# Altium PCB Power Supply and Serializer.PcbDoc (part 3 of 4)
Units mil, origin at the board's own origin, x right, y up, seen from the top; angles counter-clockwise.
Board outline 986 x 985 mil, 8 copper layers (TOP, GND1, INNER1, GND2, PWR1, INNER2, GND3, BOTTOM), stack 60.4 mil thick; 91 components, 64 nets, 288 pads, 200 vias.
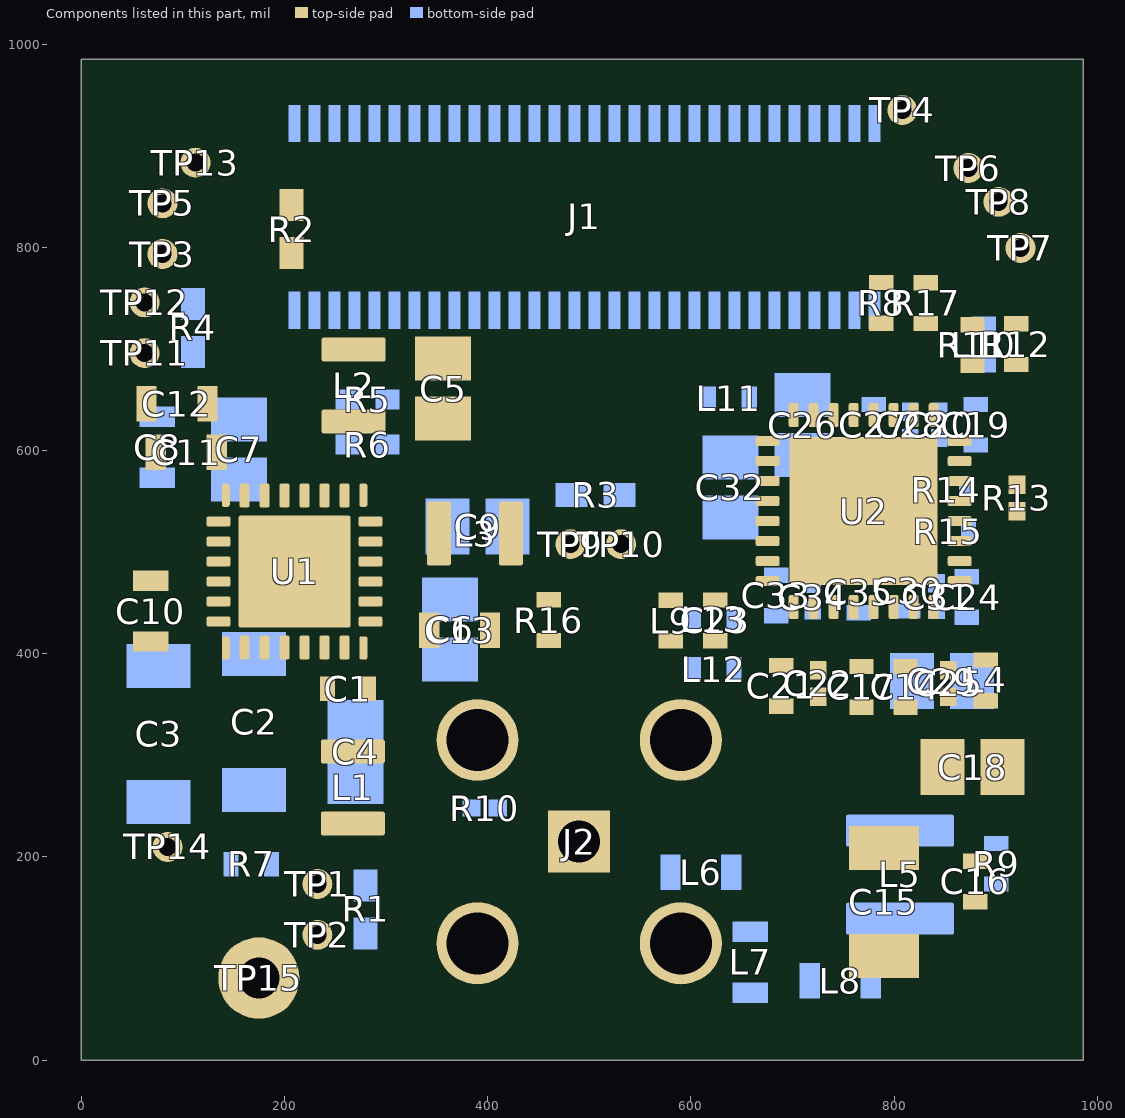
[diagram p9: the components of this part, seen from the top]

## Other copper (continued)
INNER1:
  pour cut-out: 109.26,209.8 107.4,219.16 102.1,227.1 94.16,232.4 84.8,234.26 75.44,232.4 67.5,227.1 62.2,219.16 60.34,209.8 62.2,200.44 67.5,192.5 75.44,187.2 84.8,185.34 94.16,187.2 102.1,192.5 107.4,200.44 109.26,209.8
  pour cut-out: 83.63,308.3 82.39,314.55 78.85,319.85 73.55,323.39 67.3,324.63 61.05,323.39 55.75,319.85 52.21,314.55 50.97,308.3 52.21,302.05 55.75,296.75 61.05,293.21 67.3,291.97 73.55,293.21 78.85,296.75 82.39,302.05 83.63,308.3
  pour cut-out: 126.13,308.3 124.89,314.55 121.35,319.85 116.05,323.39 109.8,324.63 103.55,323.39 98.25,319.85 94.71,314.55 93.47,308.3 94.71,302.05 98.25,296.75 103.55,293.21 109.8,291.97 116.05,293.21 121.35,296.75 124.89,302.05 126.13,308.3
  pour cut-out: 127.09,427.9 126.01,433.37 122.91,438.01 118.27,441.11 112.8,442.19 107.33,441.11 102.69,438.01 99.59,433.37 98.51,427.9 99.59,422.43 102.69,417.79 107.33,414.69 112.8,413.61 118.27,414.69 122.91,417.79 126.01,422.43 127.09,427.9
  pour cut-out: 168.63,308.3 167.39,314.55 163.85,319.85 158.55,323.39 152.3,324.63 146.05,323.39 140.75,319.85 137.21,314.55 135.97,308.3 137.21,302.05 140.75,296.75 146.05,293.21 152.3,291.97 158.55,293.21 163.85,296.75 167.39,302.05 168.63,308.3
  pour cut-out: 439.41,115.8 437.72,128.64 432.77,140.61 424.88,150.88 414.61,158.77 402.64,163.72 389.8,165.41 376.96,163.72 364.99,158.77 354.72,150.88 346.83,140.61 341.88,128.64 340.19,115.8 341.88,102.96 346.83,90.99 354.72,80.72 364.99,72.83 376.96,67.88 389.8,66.19 402.64,67.88 414.61,72.83 424.88,80.72 432.77,90.99 437.72,102.96 439.41,115.8
  pour cut-out: 323.63,205.8 322.39,212.05 318.85,217.35 313.55,220.89 307.3,222.13 301.05,220.89 295.75,217.35 292.21,212.05 290.97,205.8 292.21,199.55 295.75,194.25 301.05,190.71 307.3,189.47 313.55,190.71 318.85,194.25 322.39,199.55 323.63,205.8
  pour cut-out: 338.63,263.3 337.39,269.55 333.85,274.85 328.55,278.39 322.3,279.63 316.05,278.39 310.75,274.85 307.21,269.55 305.97,263.3 307.21,257.05 310.75,251.75 316.05,248.21 322.3,246.97 328.55,248.21 333.85,251.75 337.39,257.05 338.63,263.3
  pour cut-out: 439.41,315.8 437.72,328.64 432.77,340.61 424.88,350.88 414.61,358.77 402.64,363.72 389.8,365.41 376.96,363.72 364.99,358.77 354.72,350.88 346.83,340.61 341.88,328.64 340.19,315.8 341.88,302.96 346.83,290.99 354.72,280.72 364.99,272.83 376.96,267.88 389.8,266.19 402.64,267.88 414.61,272.83 424.88,280.72 432.77,290.99 437.72,302.96 439.41,315.8
  pour cut-out: 533.66,215.8 532.16,227.15 527.78,237.73 520.81,246.81 511.73,253.78 501.15,258.16 489.8,259.66 478.45,258.16 467.87,253.78 458.79,246.81 451.82,237.73 447.44,227.15 445.94,215.8 447.44,204.45 451.82,193.87 458.79,184.79 467.87,177.82 478.45,173.44 489.8,171.94 501.15,173.44 511.73,177.82 520.81,184.79 527.78,193.87 532.16,204.45 533.66,215.8
  pour cut-out: 639.41,115.8 637.72,128.64 632.77,140.61 624.88,150.88 614.61,158.77 602.64,163.72 589.8,165.41 576.96,163.72 564.99,158.77 554.72,150.88 546.83,140.61 541.88,128.64 540.19,115.8 541.88,102.96 546.83,90.99 554.72,80.72 564.99,72.83 576.96,67.88 589.8,66.19 602.64,67.88 614.61,72.83 624.88,80.72 632.77,90.99 637.72,102.96 639.41,115.8
  pour cut-out: 639.41,315.8 637.72,328.64 632.77,340.61 624.88,350.88 614.61,358.77 602.64,363.72 589.8,365.41 576.96,363.72 564.99,358.77 554.72,350.88 546.83,340.61 541.88,328.64 540.19,315.8 541.88,302.96 546.83,290.99 554.72,280.72 564.99,272.83 576.96,267.88 589.8,266.19 602.64,267.88 614.61,272.83 624.88,280.72 632.77,290.99 637.72,302.96 639.41,315.8
  pour cut-out: 561.13,412.71 559.89,418.96 556.35,424.26 551.05,427.8 544.8,429.04 538.55,427.8 533.25,424.26 529.71,418.96 528.47,412.71 529.71,406.46 533.25,401.16 538.55,397.62 544.8,396.38 551.05,397.62 556.35,401.16 559.89,406.46 561.13,412.71
  pour cut-out: 561.13,452.87 559.89,459.12 556.35,464.42 551.05,467.96 544.8,469.2 538.55,467.96 533.25,464.42 529.71,459.12 528.47,452.87 529.71,446.62 533.25,441.32 538.55,437.78 544.8,436.54 551.05,437.78 556.35,441.32 559.89,446.62 561.13,452.87
  pour cut-out: 724.09,410.8 723.01,416.27 719.91,420.91 715.27,424.01 709.8,425.09 704.33,424.01 699.69,420.91 696.59,416.27 695.51,410.8 696.59,405.33 699.69,400.69 704.33,397.59 709.8,396.51 715.27,397.59 719.91,400.69 723.01,405.33 724.09,410.8
  pour cut-out: 912.03,550.71 910.94,556.18 907.84,560.82 903.21,563.92 897.74,565.01 892.26,563.92 887.63,560.82 884.53,556.18 883.44,550.71 884.53,545.24 887.63,540.61 892.26,537.51 897.74,536.42 903.21,537.51 907.84,540.61 910.94,545.24 912.03,550.71
  pour cut-out: 934.09,658.3 933.01,663.77 929.91,668.41 925.27,671.51 919.8,672.59 914.33,671.51 909.69,668.41 906.59,663.77 905.51,658.3 906.59,652.83 909.69,648.19 914.33,645.09 919.8,644.01 925.27,645.09 929.91,648.19 933.01,652.83 934.09,658.3
  pour cut-out: 214.25,574.8 213.17,580.27 210.07,584.91 205.43,588.01 199.96,589.09 194.49,588.01 189.85,584.91 186.75,580.27 185.67,574.8 186.75,569.33 189.85,564.69 194.49,561.59 199.96,560.51 205.43,561.59 210.07,564.69 213.17,569.33 214.25,574.8
  pour cut-out: 275.8,575.8 274.72,581.27 271.62,585.91 266.98,589.01 261.51,590.09 256.04,589.01 251.4,585.91 248.3,581.27 247.22,575.8 248.3,570.33 251.4,565.69 256.04,562.59 261.51,561.51 266.98,562.59 271.62,565.69 274.72,570.33 275.8,575.8
  text ".Layer_Name" at 577,-858.49 h60
GND2:
  pour cut-out: 323.63,205.8 322.39,212.05 318.85,217.35 313.55,220.89 307.3,222.13 301.05,220.89 295.75,217.35 292.21,212.05 290.97,205.8 292.21,199.55 295.75,194.25 301.05,190.71 307.3,189.47 313.55,190.71 318.85,194.25 322.39,199.55 323.63,205.8
  pour cut-out: 911.96,550.94 910.87,556.41 907.77,561.05 903.14,564.15 897.67,565.24 892.2,564.15 887.56,561.05 884.46,556.41 883.37,550.94 884.46,545.47 887.56,540.83 892.2,537.73 897.67,536.65 903.14,537.73 907.77,540.83 910.87,545.47 911.96,550.94
  pour cut-out: 935.09,590.8 934.01,596.27 930.91,600.91 926.27,604.01 920.8,605.09 915.33,604.01 910.69,600.91 907.59,596.27 906.51,590.8 907.59,585.33 910.69,580.69 915.33,577.59 920.8,576.51 926.27,577.59 930.91,580.69 934.01,585.33 935.09,590.8
  pour cut-out: 774.49,893.3 773.41,898.77 770.31,903.41 765.67,906.51 760.2,907.59 754.73,906.51 750.09,903.41 746.99,898.77 745.91,893.3 746.99,887.83 750.09,883.19 754.73,880.09 760.2,879.01 765.67,880.09 770.31,883.19 773.41,887.83 774.49,893.3
  pour cut-out: 735.09,893.3 734.01,898.77 730.91,903.41 726.27,906.51 720.8,907.59 715.33,906.51 710.69,903.41 707.59,898.77 706.51,893.3 707.59,887.83 710.69,883.19 715.33,880.09 720.8,879.01 726.27,880.09 730.91,883.19 734.01,887.83 735.09,893.3
  pour cut-out: 724.09,410.8 723.01,416.27 719.91,420.91 715.27,424.01 709.8,425.09 704.33,424.01 699.69,420.91 696.59,416.27 695.51,410.8 696.59,405.33 699.69,400.69 704.33,397.59 709.8,396.51 715.27,397.59 719.91,400.69 723.01,405.33 724.09,410.8
  pour cut-out: 695.69,893.3 694.61,898.77 691.51,903.41 686.87,906.51 681.4,907.59 675.93,906.51 671.29,903.41 668.19,898.77 667.11,893.3 668.19,887.83 671.29,883.19 675.93,880.09 681.4,879.01 686.87,880.09 691.51,883.19 694.61,887.83 695.69,893.3
  pour cut-out: 561.13,452.87 559.89,459.12 556.35,464.42 551.05,467.96 544.8,469.2 538.55,467.96 533.25,464.42 529.71,459.12 528.47,452.87 529.71,446.62 533.25,441.32 538.55,437.78 544.8,436.54 551.05,437.78 556.35,441.32 559.89,446.62 561.13,452.87
  pour cut-out: 561.13,412.71 559.89,418.96 556.35,424.26 551.05,427.8 544.8,429.04 538.55,427.8 533.25,424.26 529.71,418.96 528.47,412.71 529.71,406.46 533.25,401.16 538.55,397.62 544.8,396.38 551.05,397.62 556.35,401.16 559.89,406.46 561.13,412.71
  pour cut-out: 639.41,315.8 637.72,328.64 632.77,340.61 624.88,350.88 614.61,358.77 602.64,363.72 589.8,365.41 576.96,363.72 564.99,358.77 554.72,350.88 546.83,340.61 541.88,328.64 540.19,315.8 541.88,302.96 546.83,290.99 554.72,280.72 564.99,272.83 576.96,267.88 589.8,266.19 602.64,267.88 614.61,272.83 624.88,280.72 632.77,290.99 637.72,302.96 639.41,315.8
  pour cut-out: 639.41,115.8 637.72,128.64 632.77,140.61 624.88,150.88 614.61,158.77 602.64,163.72 589.8,165.41 576.96,163.72 564.99,158.77 554.72,150.88 546.83,140.61 541.88,128.64 540.19,115.8 541.88,102.96 546.83,90.99 554.72,80.72 564.99,72.83 576.96,67.88 589.8,66.19 602.64,67.88 614.61,72.83 624.88,80.72 632.77,90.99 637.72,102.96 639.41,115.8
  pour cut-out: 477.09,385.8 476.01,391.27 472.91,395.91 468.27,399.01 462.8,400.09 457.33,399.01 452.69,395.91 449.59,391.27 448.51,385.8 449.59,380.33 452.69,375.69 457.33,372.59 462.8,371.51 468.27,372.59 472.91,375.69 476.01,380.33 477.09,385.8
  pour cut-out: 533.66,215.8 532.16,227.15 527.78,237.73 520.81,246.81 511.73,253.78 501.15,258.16 489.8,259.66 478.45,258.16 467.87,253.78 458.79,246.81 451.82,237.73 447.44,227.15 445.94,215.8 447.44,204.45 451.82,193.87 458.79,184.79 467.87,177.82 478.45,173.44 489.8,171.94 501.15,173.44 511.73,177.82 520.81,184.79 527.78,193.87 532.16,204.45 533.66,215.8
  pour cut-out: 341.39,885.8 340.31,891.27 337.21,895.91 332.57,899.01 327.1,900.09 321.63,899.01 316.99,895.91 313.89,891.27 312.81,885.8 313.89,880.33 316.99,875.69 321.63,872.59 327.1,871.51 332.57,872.59 337.21,875.69 340.31,880.33 341.39,885.8
  pour cut-out: 439.41,115.8 437.72,128.64 432.77,140.61 424.88,150.88 414.61,158.77 402.64,163.72 389.8,165.41 376.96,163.72 364.99,158.77 354.72,150.88 346.83,140.61 341.88,128.64 340.19,115.8 341.88,102.96 346.83,90.99 354.72,80.72 364.99,72.83 376.96,67.88 389.8,66.19 402.64,67.88 414.61,72.83 424.88,80.72 432.77,90.99 437.72,102.96 439.41,115.8
  pour cut-out: 266.13,865.8 264.89,872.05 261.35,877.35 256.05,880.89 249.8,882.13 243.55,880.89 238.25,877.35 234.71,872.05 233.47,865.8 234.71,859.55 238.25,854.25 243.55,850.71 249.8,849.47 256.05,850.71 261.35,854.25 264.89,859.55 266.13,865.8
  pour cut-out: 293.63,890.8 292.39,897.05 288.85,902.35 283.55,905.89 277.3,907.13 271.05,905.89 265.75,902.35 262.21,897.05 260.97,890.8 262.21,884.55 265.75,879.25 271.05,875.71 277.3,874.47 283.55,875.71 288.85,879.25 292.39,884.55 293.63,890.8
  pour cut-out: 275.8,575.8 274.72,581.27 271.62,585.91 266.98,589.01 261.51,590.09 256.04,589.01 251.4,585.91 248.3,581.27 247.22,575.8 248.3,570.33 251.4,565.69 256.04,562.59 261.51,561.51 266.98,562.59 271.62,565.69 274.72,570.33 275.8,575.8
  pour cut-out: 233.93,379.8 232.85,385.27 229.75,389.91 225.11,393.01 219.64,394.09 214.17,393.01 209.53,389.91 206.43,385.27 205.35,379.8 206.43,374.33 209.53,369.69 214.17,366.59 219.64,365.51 225.11,366.59 229.75,369.69 232.85,374.33 233.93,379.8
  pour cut-out: 214.25,574.8 213.17,580.27 210.07,584.91 205.43,588.01 199.96,589.09 194.49,588.01 189.85,584.91 186.75,580.27 185.67,574.8 186.75,569.33 189.85,564.69 194.49,561.59 199.96,560.51 205.43,561.59 210.07,564.69 213.17,569.33 214.25,574.8
  pour cut-out: 211.13,308.3 209.89,314.55 206.35,319.85 201.05,323.39 194.8,324.63 188.55,323.39 183.25,319.85 179.71,314.55 178.47,308.3 179.71,302.05 183.25,296.75 188.55,293.21 194.8,291.97 201.05,293.21 206.35,296.75 209.89,302.05 211.13,308.3
  pour cut-out: 168.63,308.3 167.39,314.55 163.85,319.85 158.55,323.39 152.3,324.63 146.05,323.39 140.75,319.85 137.21,314.55 135.97,308.3 137.21,302.05 140.75,296.75 146.05,293.21 152.3,291.97 158.55,293.21 163.85,296.75 167.39,302.05 168.63,308.3
  pour cut-out: 161.43,220.8 160.35,226.27 157.25,230.91 152.61,234.01 147.14,235.09 141.67,234.01 137.03,230.91 133.93,226.27 132.85,220.8 133.93,215.33 137.03,210.69 141.67,207.59 147.14,206.51 152.61,207.59 157.25,210.69 160.35,215.33 161.43,220.8
  pour cut-out: 127.09,427.9 126.01,433.37 122.91,438.01 118.27,441.11 112.8,442.19 107.33,441.11 102.69,438.01 99.59,433.37 98.51,427.9 99.59,422.43 102.69,417.79 107.33,414.69 112.8,413.61 118.27,414.69 122.91,417.79 126.01,422.43 127.09,427.9
  pour cut-out: 126.13,308.3 124.89,314.55 121.35,319.85 116.05,323.39 109.8,324.63 103.55,323.39 98.25,319.85 94.71,314.55 93.47,308.3 94.71,302.05 98.25,296.75 103.55,293.21 109.8,291.97 116.05,293.21 121.35,296.75 124.89,302.05 126.13,308.3
  pour cut-out: 83.63,308.3 82.39,314.55 78.85,319.85 73.55,323.39 67.3,324.63 61.05,323.39 55.75,319.85 52.21,314.55 50.97,308.3 52.21,302.05 55.75,296.75 61.05,293.21 67.3,291.97 73.55,293.21 78.85,296.75 82.39,302.05 83.63,308.3
  pour cut-out: 109.26,209.8 107.4,219.16 102.1,227.1 94.16,232.4 84.8,234.26 75.44,232.4 67.5,227.1 62.2,219.16 60.34,209.8 62.2,200.44 67.5,192.5 75.44,187.2 84.8,185.34 94.16,187.2 102.1,192.5 107.4,200.44 109.26,209.8
  pour cut-out: 327.09,680.8 326.01,686.27 322.91,690.91 318.27,694.01 312.8,695.09 307.33,694.01 302.69,690.91 299.59,686.27 298.51,680.8 299.59,675.33 302.69,670.69 307.33,667.59 312.8,666.51 318.27,667.59 322.91,670.69 326.01,675.33 327.09,680.8
  pour cut-out: 934.09,658.3 933.01,663.77 929.91,668.41 925.27,671.51 919.8,672.59 914.33,671.51 909.69,668.41 906.59,663.77 905.51,658.3 906.59,652.83 909.69,648.19 914.33,645.09 919.8,644.01 925.27,645.09 929.91,648.19 933.01,652.83 934.09,658.3
  pour cut-out: 239.09,253.3 238.01,258.77 234.91,263.41 230.27,266.51 224.8,267.59 219.33,266.51 214.69,263.41 211.59,258.77 210.51,253.3 211.59,247.83 214.69,243.19 219.33,240.09 224.8,239.01 230.27,240.09 234.91,243.19 238.01,247.83 239.09,253.3
  pour cut-out: 201.59,220.3 200.51,225.77 197.41,230.41 192.77,233.51 187.3,234.59 181.83,233.51 177.19,230.41 174.09,225.77 173.01,220.3 174.09,214.83 177.19,210.19 181.83,207.09 187.3,206.01 192.77,207.09 197.41,210.19 200.51,214.83 201.59,220.3
  pour cut-out: 338.63,263.3 337.39,269.55 333.85,274.85 328.55,278.39 322.3,279.63 316.05,278.39 310.75,274.85 307.21,269.55 305.97,263.3 307.21,257.05 310.75,251.75 316.05,248.21 322.3,246.97 328.55,248.21 333.85,251.75 337.39,257.05 338.63,263.3
  pour cut-out: 439.41,315.8 437.72,328.64 432.77,340.61 424.88,350.88 414.61,358.77 402.64,363.72 389.8,365.41 376.96,363.72 364.99,358.77 354.72,350.88 346.83,340.61 341.88,328.64 340.19,315.8 341.88,302.96 346.83,290.99 354.72,280.72 364.99,272.83 376.96,267.88 389.8,266.19 402.64,267.88 414.61,272.83 424.88,280.72 432.77,290.99 437.72,302.96 439.41,315.8
  text ".Layer_Name" at 577,-858.49 h60
PWR1:
  pour cut-out: 416.59,393.3 415.51,398.77 412.41,403.41 407.77,406.51 402.3,407.59 396.83,406.51 392.19,403.41 389.09,398.77 388.01,393.3 389.09,387.83 392.19,383.19 396.83,380.09 402.3,379.01 407.77,380.09 412.41,383.19 415.51,387.83 416.59,393.3
  pour cut-out: 338.63,263.3 337.39,269.55 333.85,274.85 328.55,278.39 322.3,279.63 316.05,278.39 310.75,274.85 307.21,269.55 305.97,263.3 307.21,257.05 310.75,251.75 316.05,248.21 322.3,246.97 328.55,248.21 333.85,251.75 337.39,257.05 338.63,263.3
  pour cut-out: 323.63,205.8 322.39,212.05 318.85,217.35 313.55,220.89 307.3,222.13 301.05,220.89 295.75,217.35 292.21,212.05 290.97,205.8 292.21,199.55 295.75,194.25 301.05,190.71 307.3,189.47 313.55,190.71 318.85,194.25 322.39,199.55 323.63,205.8
  pour cut-out: 275.8,575.8 274.72,581.27 271.62,585.91 266.98,589.01 261.51,590.09 256.04,589.01 251.4,585.91 248.3,581.27 247.22,575.8 248.3,570.33 251.4,565.69 256.04,562.59 261.51,561.51 266.98,562.59 271.62,565.69 274.72,570.33 275.8,575.8
  pour cut-out: 224.09,520.8 223.01,526.27 219.91,530.91 215.27,534.01 209.8,535.09 204.33,534.01 199.69,530.91 196.59,526.27 195.51,520.8 196.59,515.33 199.69,510.69 204.33,507.59 209.8,506.51 215.27,507.59 219.91,510.69 223.01,515.33 224.09,520.8
  pour cut-out: 264.09,520.8 263.01,526.27 259.91,530.91 255.27,534.01 249.8,535.09 244.33,534.01 239.69,530.91 236.59,526.27 235.51,520.8 236.59,515.33 239.69,510.69 244.33,507.59 249.8,506.51 255.27,507.59 259.91,510.69 263.01,515.33 264.09,520.8
  pour cut-out: 224.09,440.8 223.01,446.27 219.91,450.91 215.27,454.01 209.8,455.09 204.33,454.01 199.69,450.91 196.59,446.27 195.51,440.8 196.59,435.33 199.69,430.69 204.33,427.59 209.8,426.51 215.27,427.59 219.91,430.69 223.01,435.33 224.09,440.8
  pour cut-out: 264.09,440.8 263.01,446.27 259.91,450.91 255.27,454.01 249.8,455.09 244.33,454.01 239.69,450.91 236.59,446.27 235.51,440.8 236.59,435.33 239.69,430.69 244.33,427.59 249.8,426.51 255.27,427.59 259.91,430.69 263.01,435.33 264.09,440.8
  pour cut-out: 264.09,480.8 263.01,486.27 259.91,490.91 255.27,494.01 249.8,495.09 244.33,494.01 239.69,490.91 236.59,486.27 235.51,480.8 236.59,475.33 239.69,470.69 244.33,467.59 249.8,466.51 255.27,467.59 259.91,470.69 263.01,475.33 264.09,480.8
  pour cut-out: 224.09,480.8 223.01,486.27 219.91,490.91 215.27,494.01 209.8,495.09 204.33,494.01 199.69,490.91 196.59,486.27 195.51,480.8 196.59,475.33 199.69,470.69 204.33,467.59 209.8,466.51 215.27,467.59 219.91,470.69 223.01,475.33 224.09,480.8
  pour cut-out: 233.93,379.8 232.85,385.27 229.75,389.91 225.11,393.01 219.64,394.09 214.17,393.01 209.53,389.91 206.43,385.27 205.35,379.8 206.43,374.33 209.53,369.69 214.17,366.59 219.64,365.51 225.11,366.59 229.75,369.69 232.85,374.33 233.93,379.8
  pour cut-out: 239.09,253.3 238.01,258.77 234.91,263.41 230.27,266.51 224.8,267.59 219.33,266.51 214.69,263.41 211.59,258.77 210.51,253.3 211.59,247.83 214.69,243.19 219.33,240.09 224.8,239.01 230.27,240.09 234.91,243.19 238.01,247.83 239.09,253.3
  pour cut-out: 214.25,574.8 213.17,580.27 210.07,584.91 205.43,588.01 199.96,589.09 194.49,588.01 189.85,584.91 186.75,580.27 185.67,574.8 186.75,569.33 189.85,564.69 194.49,561.59 199.96,560.51 205.43,561.59 210.07,564.69 213.17,569.33 214.25,574.8
  pour cut-out: 184.09,520.8 183.01,526.27 179.91,530.91 175.27,534.01 169.8,535.09 164.33,534.01 159.69,530.91 156.59,526.27 155.51,520.8 156.59,515.33 159.69,510.69 164.33,507.59 169.8,506.51 175.27,507.59 179.91,510.69 183.01,515.33 184.09,520.8
  pour cut-out: 184.09,440.8 183.01,446.27 179.91,450.91 175.27,454.01 169.8,455.09 164.33,454.01 159.69,450.91 156.59,446.27 155.51,440.8 156.59,435.33 159.69,430.69 164.33,427.59 169.8,426.51 175.27,427.59 179.91,430.69 183.01,435.33 184.09,440.8
  pour cut-out: 184.09,480.8 183.01,486.27 179.91,490.91 175.27,494.01 169.8,495.09 164.33,494.01 159.69,490.91 156.59,486.27 155.51,480.8 156.59,475.33 159.69,470.69 164.33,467.59 169.8,466.51 175.27,467.59 179.91,470.69 183.01,475.33 184.09,480.8
  pour cut-out: 184.09,350.8 183.01,356.27 179.91,360.91 175.27,364.01 169.8,365.09 164.33,364.01 159.69,360.91 156.59,356.27 155.51,350.8 156.59,345.33 159.69,340.69 164.33,337.59 169.8,336.51 175.27,337.59 179.91,340.69 183.01,345.33 184.09,350.8
  pour cut-out: 211.13,308.3 209.89,314.55 206.35,319.85 201.05,323.39 194.8,324.63 188.55,323.39 183.25,319.85 179.71,314.55 178.47,308.3 179.71,302.05 183.25,296.75 188.55,293.21 194.8,291.97 201.05,293.21 206.35,296.75 209.89,302.05 211.13,308.3
  pour cut-out: 168.63,308.3 167.39,314.55 163.85,319.85 158.55,323.39 152.3,324.63 146.05,323.39 140.75,319.85 137.21,314.55 135.97,308.3 137.21,302.05 140.75,296.75 146.05,293.21 152.3,291.97 158.55,293.21 163.85,296.75 167.39,302.05 168.63,308.3
  pour cut-out: 161.43,220.8 160.35,226.27 157.25,230.91 152.61,234.01 147.14,235.09 141.67,234.01 137.03,230.91 133.93,226.27 132.85,220.8 133.93,215.33 137.03,210.69 141.67,207.59 147.14,206.51 152.61,207.59 157.25,210.69 160.35,215.33 161.43,220.8
  pour cut-out: 201.59,220.3 200.51,225.77 197.41,230.41 192.77,233.51 187.3,234.59 181.83,233.51 177.19,230.41 174.09,225.77 173.01,220.3 174.09,214.83 177.19,210.19 181.83,207.09 187.3,206.01 192.77,207.09 197.41,210.19 200.51,214.83 201.59,220.3
  pour cut-out: 128.59,561.3 127.51,566.77 124.41,571.41 119.77,574.51 114.3,575.59 108.83,574.51 104.19,571.41 101.09,566.77 100.01,561.3 101.09,555.83 104.19,551.19 108.83,548.09 114.3,547.01 119.77,548.09 124.41,551.19 127.51,555.83 128.59,561.3
  pour cut-out: 89.09,350.8 88.01,356.27 84.91,360.91 80.27,364.01 74.8,365.09 69.33,364.01 64.69,360.91 61.59,356.27 60.51,350.8 61.59,345.33 64.69,340.69 69.33,337.59 74.8,336.51 80.27,337.59 84.91,340.69 88.01,345.33 89.09,350.8
  pour cut-out: 126.13,308.3 124.89,314.55 121.35,319.85 116.05,323.39 109.8,324.63 103.55,323.39 98.25,319.85 94.71,314.55 93.47,308.3 94.71,302.05 98.25,296.75 103.55,293.21 109.8,291.97 116.05,293.21 121.35,296.75 124.89,302.05 126.13,308.3
  pour cut-out: 83.63,308.3 82.39,314.55 78.85,319.85 73.55,323.39 67.3,324.63 61.05,323.39 55.75,319.85 52.21,314.55 50.97,308.3 52.21,302.05 55.75,296.75 61.05,293.21 67.3,291.97 73.55,293.21 78.85,296.75 82.39,302.05 83.63,308.3
  pour cut-out: 109.26,209.8 107.4,219.16 102.1,227.1 94.16,232.4 84.8,234.26 75.44,232.4 67.5,227.1 62.2,219.16 60.34,209.8 62.2,200.44 67.5,192.5 75.44,187.2 84.8,185.34 94.16,187.2 102.1,192.5 107.4,200.44 109.26,209.8
  pour cut-out: 912.14,550.64 911.05,556.11 907.95,560.74 903.32,563.84 897.85,564.93 892.38,563.84 887.74,560.74 884.64,556.11 883.55,550.64 884.64,545.17 887.74,540.53 892.38,537.43 897.85,536.34 903.32,537.43 907.95,540.53 911.05,545.17 912.14,550.64
  pour cut-out: 824.09,268.3 823.01,273.77 819.91,278.41 815.27,281.51 809.8,282.59 804.33,281.51 799.69,278.41 796.59,273.77 795.51,268.3 796.59,262.83 799.69,258.19 804.33,255.09 809.8,254.01 815.27,255.09 819.91,258.19 823.01,262.83 824.09,268.3
  pour cut-out: 735.09,893.3 734.01,898.77 730.91,903.41 726.27,906.51 720.8,907.59 715.33,906.51 710.69,903.41 707.59,898.77 706.51,893.3 707.59,887.83 710.69,883.19 715.33,880.09 720.8,879.01 726.27,880.09 730.91,883.19 734.01,887.83 735.09,893.3
  pour cut-out: 724.09,410.8 723.01,416.27 719.91,420.91 715.27,424.01 709.8,425.09 704.33,424.01 699.69,420.91 696.59,416.27 695.51,410.8 696.59,405.33 699.69,400.69 704.33,397.59 709.8,396.51 715.27,397.59 719.91,400.69 723.01,405.33 724.09,410.8
  pour cut-out: 728.63,123.3 727.39,129.55 723.85,134.85 718.55,138.39 712.3,139.63 706.05,138.39 700.75,134.85 697.21,129.55 695.97,123.3 697.21,117.05 700.75,111.75 706.05,108.21 712.3,106.97 718.55,108.21 723.85,111.75 727.39,117.05 728.63,123.3
  pour cut-out: 695.69,893.3 694.61,898.77 691.51,903.41 686.87,906.51 681.4,907.59 675.93,906.51 671.29,903.41 668.19,898.77 667.11,893.3 668.19,887.83 671.29,883.19 675.93,880.09 681.4,879.01 686.87,880.09 691.51,883.19 694.61,887.83 695.69,893.3
  pour cut-out: 674.09,690.8 673.01,696.27 669.91,700.91 665.27,704.01 659.8,705.09 654.33,704.01 649.69,700.91 646.59,696.27 645.51,690.8 646.59,685.33 649.69,680.69 654.33,677.59 659.8,676.51 665.27,677.59 669.91,680.69 673.01,685.33 674.09,690.8
  pour cut-out: 674.09,343.22 673.01,348.69 669.91,353.33 665.27,356.43 659.8,357.51 654.33,356.43 649.69,353.33 646.59,348.69 645.51,343.22 646.59,337.75 649.69,333.11 654.33,330.01 659.8,328.93 665.27,330.01 669.91,333.11 673.01,337.75 674.09,343.22
  pour cut-out: 701.13,220.8 699.89,227.05 696.35,232.35 691.05,235.89 684.8,237.13 678.55,235.89 673.25,232.35 669.71,227.05 668.47,220.8 669.71,214.55 673.25,209.25 678.55,205.71 684.8,204.47 691.05,205.71 696.35,209.25 699.89,214.55 701.13,220.8
  pour cut-out: 713.63,168.3 712.39,174.55 708.85,179.85 703.55,183.39 697.3,184.63 691.05,183.39 685.75,179.85 682.21,174.55 680.97,168.3 682.21,162.05 685.75,156.75 691.05,153.21 697.3,151.97 703.55,153.21 708.85,156.75 712.39,162.05 713.63,168.3
  pour cut-out: 639.62,315.8 637.92,328.69 632.94,340.71 625.03,351.03 614.71,358.94 602.69,363.92 589.8,365.62 576.91,363.92 564.89,358.94 554.57,351.03 546.66,340.71 541.68,328.69 539.98,315.8 541.68,302.91 546.66,290.89 554.57,280.57 564.89,272.66 576.91,267.68 589.8,265.98 602.69,267.68 614.71,272.66 625.03,280.57 632.94,290.89 637.92,302.91 639.62,315.8
  pour cut-out: 518.59,704.7 517.51,710.17 514.41,714.81 509.77,717.91 504.3,718.99 498.83,717.91 494.19,714.81 491.09,710.17 490.01,704.7 491.09,699.23 494.19,694.59 498.83,691.49 504.3,690.41 509.77,691.49 514.41,694.59 517.51,699.23 518.59,704.7
  pour cut-out: 529.09,320.8 528.01,326.27 524.91,330.91 520.27,334.01 514.8,335.09 509.33,334.01 504.69,330.91 501.59,326.27 500.51,320.8 501.59,315.33 504.69,310.69 509.33,307.59 514.8,306.51 520.27,307.59 524.91,310.69 528.01,315.33 529.09,320.8
  pour cut-out: 529.09,110.8 528.01,116.27 524.91,120.91 520.27,124.01 514.8,125.09 509.33,124.01 504.69,120.91 501.59,116.27 500.51,110.8 501.59,105.33 504.69,100.69 509.33,97.59 514.8,96.51 520.27,97.59 524.91,100.69 528.01,105.33 529.09,110.8
  pour cut-out: 391.59,788.3 390.51,793.77 387.41,798.41 382.77,801.51 377.3,802.59 371.83,801.51 367.19,798.41 364.09,793.77 363.01,788.3 364.09,782.83 367.19,778.19 371.83,775.09 377.3,774.01 382.77,775.09 387.41,778.19 390.51,782.83 391.59,788.3
  pour cut-out: 341.39,885.8 340.31,891.27 337.21,895.91 332.57,899.01 327.1,900.09 321.63,899.01 316.99,895.91 313.89,891.27 312.81,885.8 313.89,880.33 316.99,875.69 321.63,872.59 327.1,871.51 332.57,872.59 337.21,875.69 340.31,880.33 341.39,885.8
  text ".Layer_Name" at 577,-858.49 h60
INNER2:
  pour cut-out: 533.66,215.8 532.16,227.15 527.78,237.73 520.81,246.81 511.73,253.78 501.15,258.16 489.8,259.66 478.45,258.16 467.87,253.78 458.79,246.81 451.82,237.73 447.44,227.15 445.94,215.8 447.44,204.45 451.82,193.87 458.79,184.79 467.87,177.82 478.45,173.44 489.8,171.94 501.15,173.44 511.73,177.82 520.81,184.79 527.78,193.87 532.16,204.45 533.66,215.8
  pour cut-out: 109.06,209.8 107.21,219.08 101.95,226.95 94.08,232.21 84.8,234.06 75.52,232.21 67.65,226.95 62.39,219.08 60.54,209.8 62.39,200.52 67.65,192.65 75.52,187.39 84.8,185.54 94.08,187.39 101.95,192.65 107.21,200.52 109.06,209.8
  pour cut-out: 89.09,350.8 88.01,356.27 84.91,360.91 80.27,364.01 74.8,365.09 69.33,364.01 64.69,360.91 61.59,356.27 60.51,350.8 61.59,345.33 64.69,340.69 69.33,337.59 74.8,336.51 80.27,337.59 84.91,340.69 88.01,345.33 89.09,350.8
  pour cut-out: 128.59,561.3 127.51,566.77 124.41,571.41 119.77,574.51 114.3,575.59 108.83,574.51 104.19,571.41 101.09,566.77 100.01,561.3 101.09,555.83 104.19,551.19 108.83,548.09 114.3,547.01 119.77,548.09 124.41,551.19 127.51,555.83 128.59,561.3
  pour cut-out: 201.59,220.3 200.51,225.77 197.41,230.41 192.77,233.51 187.3,234.59 181.83,233.51 177.19,230.41 174.09,225.77 173.01,220.3 174.09,214.83 177.19,210.19 181.83,207.09 187.3,206.01 192.77,207.09 197.41,210.19 200.51,214.83 201.59,220.3
  pour cut-out: 161.43,220.8 160.35,226.27 157.25,230.91 152.61,234.01 147.14,235.09 141.67,234.01 137.03,230.91 133.93,226.27 132.85,220.8 133.93,215.33 137.03,210.69 141.67,207.59 147.14,206.51 152.61,207.59 157.25,210.69 160.35,215.33 161.43,220.8
  pour cut-out: 184.09,480.8 183.01,486.27 179.91,490.91 175.27,494.01 169.8,495.09 164.33,494.01 159.69,490.91 156.59,486.27 155.51,480.8 156.59,475.33 159.69,470.69 164.33,467.59 169.8,466.51 175.27,467.59 179.91,470.69 183.01,475.33 184.09,480.8
  pour cut-out: 184.09,440.8 183.01,446.27 179.91,450.91 175.27,454.01 169.8,455.09 164.33,454.01 159.69,450.91 156.59,446.27 155.51,440.8 156.59,435.33 159.69,430.69 164.33,427.59 169.8,426.51 175.27,427.59 179.91,430.69 183.01,435.33 184.09,440.8
  pour cut-out: 184.09,520.8 183.01,526.27 179.91,530.91 175.27,534.01 169.8,535.09 164.33,534.01 159.69,530.91 156.59,526.27 155.51,520.8 156.59,515.33 159.69,510.69 164.33,507.59 169.8,506.51 175.27,507.59 179.91,510.69 183.01,515.33 184.09,520.8
  pour cut-out: 214.25,574.8 213.17,580.27 210.07,584.91 205.43,588.01 199.96,589.09 194.49,588.01 189.85,584.91 186.75,580.27 185.67,574.8 186.75,569.33 189.85,564.69 194.49,561.59 199.96,560.51 205.43,561.59 210.07,564.69 213.17,569.33 214.25,574.8
  pour cut-out: 239.09,253.3 238.01,258.77 234.91,263.41 230.27,266.51 224.8,267.59 219.33,266.51 214.69,263.41 211.59,258.77 210.51,253.3 211.59,247.83 214.69,243.19 219.33,240.09 224.8,239.01 230.27,240.09 234.91,243.19 238.01,247.83 239.09,253.3
  pour cut-out: 224.09,480.8 223.01,486.27 219.91,490.91 215.27,494.01 209.8,495.09 204.33,494.01 199.69,490.91 196.59,486.27 195.51,480.8 196.59,475.33 199.69,470.69 204.33,467.59 209.8,466.51 215.27,467.59 219.91,470.69 223.01,475.33 224.09,480.8
  pour cut-out: 264.09,480.8 263.01,486.27 259.91,490.91 255.27,494.01 249.8,495.09 244.33,494.01 239.69,490.91 236.59,486.27 235.51,480.8 236.59,475.33 239.69,470.69 244.33,467.59 249.8,466.51 255.27,467.59 259.91,470.69 263.01,475.33 264.09,480.8
  pour cut-out: 264.09,440.8 263.01,446.27 259.91,450.91 255.27,454.01 249.8,455.09 244.33,454.01 239.69,450.91 236.59,446.27 235.51,440.8 236.59,435.33 239.69,430.69 244.33,427.59 249.8,426.51 255.27,427.59 259.91,430.69 263.01,435.33 264.09,440.8
  pour cut-out: 224.09,440.8 223.01,446.27 219.91,450.91 215.27,454.01 209.8,455.09 204.33,454.01 199.69,450.91 196.59,446.27 195.51,440.8 196.59,435.33 199.69,430.69 204.33,427.59 209.8,426.51 215.27,427.59 219.91,430.69 223.01,435.33 224.09,440.8
  pour cut-out: 264.09,520.8 263.01,526.27 259.91,530.91 255.27,534.01 249.8,535.09 244.33,534.01 239.69,530.91 236.59,526.27 235.51,520.8 236.59,515.33 239.69,510.69 244.33,507.59 249.8,506.51 255.27,507.59 259.91,510.69 263.01,515.33 264.09,520.8
  pour cut-out: 224.09,520.8 223.01,526.27 219.91,530.91 215.27,534.01 209.8,535.09 204.33,534.01 199.69,530.91 196.59,526.27 195.51,520.8 196.59,515.33 199.69,510.69 204.33,507.59 209.8,506.51 215.27,507.59 219.91,510.69 223.01,515.33 224.09,520.8
  pour cut-out: 275.8,575.8 274.72,581.27 271.62,585.91 266.98,589.01 261.51,590.09 256.04,589.01 251.4,585.91 248.3,581.27 247.22,575.8 248.3,570.33 251.4,565.69 256.04,562.59 261.51,561.51 266.98,562.59 271.62,565.69 274.72,570.33 275.8,575.8
  pour cut-out: 262.69,770.8 261.61,776.27 258.51,780.91 253.87,784.01 248.4,785.09 242.93,784.01 238.29,780.91 235.19,776.27 234.11,770.8 235.19,765.33 238.29,760.69 242.93,757.59 248.4,756.51 253.87,757.59 258.51,760.69 261.61,765.33 262.69,770.8
  pour cut-out: 293.63,890.8 292.39,897.05 288.85,902.35 283.55,905.89 277.3,907.13 271.05,905.89 265.75,902.35 262.21,897.05 260.97,890.8 262.21,884.55 265.75,879.25 271.05,875.71 277.3,874.47 283.55,875.71 288.85,879.25 292.39,884.55 293.63,890.8
  pour cut-out: 266.13,865.8 264.89,872.05 261.35,877.35 256.05,880.89 249.8,882.13 243.55,880.89 238.25,877.35 234.71,872.05 233.47,865.8 234.71,859.55 238.25,854.25 243.55,850.71 249.8,849.47 256.05,850.71 261.35,854.25 264.89,859.55 266.13,865.8
  pour cut-out: 439.62,115.8 437.92,128.69 432.94,140.71 425.03,151.03 414.71,158.94 402.69,163.92 389.8,165.62 376.91,163.92 364.89,158.94 354.57,151.03 346.66,140.71 341.68,128.69 339.98,115.8 341.68,102.91 346.66,90.89 354.57,80.57 364.89,72.66 376.91,67.68 389.8,65.98 402.69,67.68 414.71,72.66 425.03,80.57 432.94,90.89 437.92,102.91 439.62,115.8
  pour cut-out: 323.63,205.8 322.39,212.05 318.85,217.35 313.55,220.89 307.3,222.13 301.05,220.89 295.75,217.35 292.21,212.05 290.97,205.8 292.21,199.55 295.75,194.25 301.05,190.71 307.3,189.47 313.55,190.71 318.85,194.25 322.39,199.55 323.63,205.8
  pour cut-out: 341.39,885.8 340.31,891.27 337.21,895.91 332.57,899.01 327.1,900.09 321.63,899.01 316.99,895.91 313.89,891.27 312.81,885.8 313.89,880.33 316.99,875.69 321.63,872.59 327.1,871.51 332.57,872.59 337.21,875.69 340.31,880.33 341.39,885.8
  pour cut-out: 416.59,393.3 415.51,398.77 412.41,403.41 407.77,406.51 402.3,407.59 396.83,406.51 392.19,403.41 389.09,398.77 388.01,393.3 389.09,387.83 392.19,383.19 396.83,380.09 402.3,379.01 407.77,380.09 412.41,383.19 415.51,387.83 416.59,393.3
  pour cut-out: 391.59,788.3 390.51,793.77 387.41,798.41 382.77,801.51 377.3,802.59 371.83,801.51 367.19,798.41 364.09,793.77 363.01,788.3 364.09,782.83 367.19,778.19 371.83,775.09 377.3,774.01 382.77,775.09 387.41,778.19 390.51,782.83 391.59,788.3
  pour cut-out: 529.09,110.8 528.01,116.27 524.91,120.91 520.27,124.01 514.8,125.09 509.33,124.01 504.69,120.91 501.59,116.27 500.51,110.8 501.59,105.33 504.69,100.69 509.33,97.59 514.8,96.51 520.27,97.59 524.91,100.69 528.01,105.33 529.09,110.8
  pour cut-out: 479.09,110.8 478.01,116.27 474.91,120.91 470.27,124.01 464.8,125.09 459.33,124.01 454.69,120.91 451.59,116.27 450.51,110.8 451.59,105.33 454.69,100.69 459.33,97.59 464.8,96.51 470.27,97.59 474.91,100.69 478.01,105.33 479.09,110.8
  pour cut-out: 479.09,320.8 478.01,326.27 474.91,330.91 470.27,334.01 464.8,335.09 459.33,334.01 454.69,330.91 451.59,326.27 450.51,320.8 451.59,315.33 454.69,310.69 459.33,307.59 464.8,306.51 470.27,307.59 474.91,310.69 478.01,315.33 479.09,320.8
  pour cut-out: 529.09,320.8 528.01,326.27 524.91,330.91 520.27,334.01 514.8,335.09 509.33,334.01 504.69,330.91 501.59,326.27 500.51,320.8 501.59,315.33 504.69,310.69 509.33,307.59 514.8,306.51 520.27,307.59 524.91,310.69 528.01,315.33 529.09,320.8
  pour cut-out: 477.09,385.8 476.01,391.27 472.91,395.91 468.27,399.01 462.8,400.09 457.33,399.01 452.69,395.91 449.59,391.27 448.51,385.8 449.59,380.33 452.69,375.69 457.33,372.59 462.8,371.51 468.27,372.59 472.91,375.69 476.01,380.33 477.09,385.8
  pour cut-out: 518.59,704.7 517.51,710.17 514.41,714.81 509.77,717.91 504.3,718.99 498.83,717.91 494.19,714.81 491.09,710.17 490.01,704.7 491.09,699.23 494.19,694.59 498.83,691.49 504.3,690.41 509.77,691.49 514.41,694.59 517.51,699.23 518.59,704.7
  pour cut-out: 639.62,315.8 637.92,328.69 632.94,340.71 625.03,351.03 614.71,358.94 602.69,363.92 589.8,365.62 576.91,363.92 564.89,358.94 554.57,351.03 546.66,340.71 541.68,328.69 539.98,315.8 541.68,302.91 546.66,290.89 554.57,280.57 564.89,272.66 576.91,267.68 589.8,265.98 602.69,267.68 614.71,272.66 625.03,280.57 632.94,290.89 637.92,302.91 639.62,315.8
  pour cut-out: 561.13,412.71 559.89,418.96 556.35,424.26 551.05,427.8 544.8,429.04 538.55,427.8 533.25,424.26 529.71,418.96 528.47,412.71 529.71,406.46 533.25,401.16 538.55,397.62 544.8,396.38 551.05,397.62 556.35,401.16 559.89,406.46 561.13,412.71
  pour cut-out: 561.13,452.87 559.89,459.12 556.35,464.42 551.05,467.96 544.8,469.2 538.55,467.96 533.25,464.42 529.71,459.12 528.47,452.87 529.71,446.62 533.25,441.32 538.55,437.78 544.8,436.54 551.05,437.78 556.35,441.32 559.89,446.62 561.13,452.87
  pour cut-out: 713.63,168.3 712.39,174.55 708.85,179.85 703.55,183.39 697.3,184.63 691.05,183.39 685.75,179.85 682.21,174.55 680.97,168.3 682.21,162.05 685.75,156.75 691.05,153.21 697.3,151.97 703.55,153.21 708.85,156.75 712.39,162.05 713.63,168.3
  pour cut-out: 701.13,220.8 699.89,227.05 696.35,232.35 691.05,235.89 684.8,237.13 678.55,235.89 673.25,232.35 669.71,227.05 668.47,220.8 669.71,214.55 673.25,209.25 678.55,205.71 684.8,204.47 691.05,205.71 696.35,209.25 699.89,214.55 701.13,220.8
  pour cut-out: 674.09,343.22 673.01,348.69 669.91,353.33 665.27,356.43 659.8,357.51 654.33,356.43 649.69,353.33 646.59,348.69 645.51,343.22 646.59,337.75 649.69,333.11 654.33,330.01 659.8,328.93 665.27,330.01 669.91,333.11 673.01,337.75 674.09,343.22
  pour cut-out: 674.09,690.8 673.01,696.27 669.91,700.91 665.27,704.01 659.8,705.09 654.33,704.01 649.69,700.91 646.59,696.27 645.51,690.8 646.59,685.33 649.69,680.69 654.33,677.59 659.8,676.51 665.27,677.59 669.91,680.69 673.01,685.33 674.09,690.8
  pour cut-out: 728.63,123.3 727.39,129.55 723.85,134.85 718.55,138.39 712.3,139.63 706.05,138.39 700.75,134.85 697.21,129.55 695.97,123.3 697.21,117.05 700.75,111.75 706.05,108.21 712.3,106.97 718.55,108.21 723.85,111.75 727.39,117.05 728.63,123.3
  pour cut-out: 724.09,410.8 723.01,416.27 719.91,420.91 715.27,424.01 709.8,425.09 704.33,424.01 699.69,420.91 696.59,416.27 695.51,410.8 696.59,405.33 699.69,400.69 704.33,397.59 709.8,396.51 715.27,397.59 719.91,400.69 723.01,405.33 724.09,410.8
  pour cut-out: 824.09,268.3 823.01,273.77 819.91,278.41 815.27,281.51 809.8,282.59 804.33,281.51 799.69,278.41 796.59,273.77 795.51,268.3 796.59,262.83 799.69,258.19 804.33,255.09 809.8,254.01 815.27,255.09 819.91,258.19 823.01,262.83 824.09,268.3
  text ".Layer_Name" at 577,-858.49 h60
